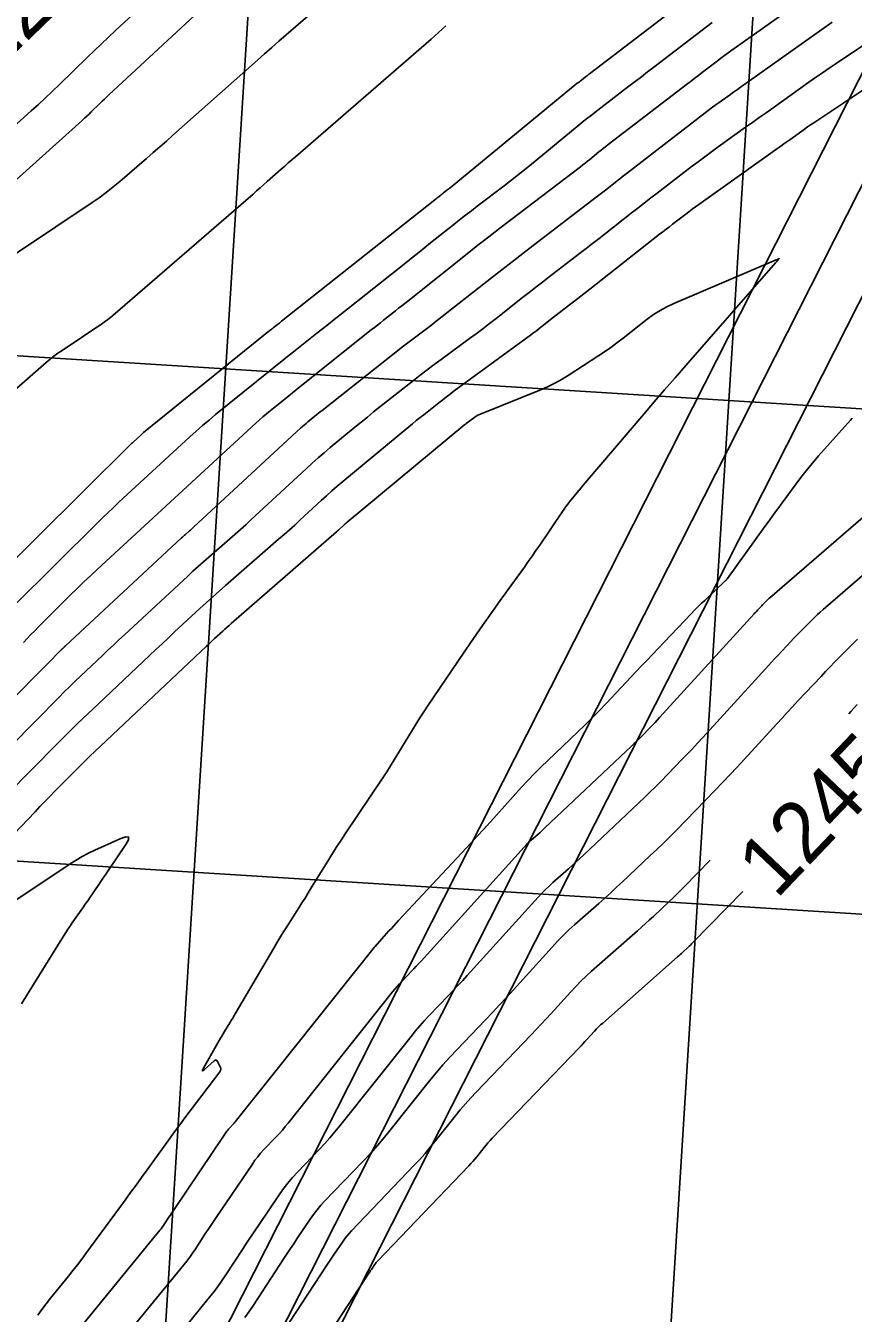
# Model space of a CAD drawing. Extents: x 658976 to 668726, y 639543 to 647196.
# Drawn here: x 662213 to 662295, y 641921 to 642048.7 of the extents above; entities that cross this region are included whole.
import ezdxf

# ---------------------------------------------------------------- set-up
doc = ezdxf.new("R2010")
doc.units = 0
for name, color, linetype in [('Ex_Contour Labels', 7, 'Continuous'), ('Ex_Major Contours', 7, 'Continuous'), ('Ex_Minor Contours', 7, 'Continuous'), ('R_Grid', 7, 'Continuous'), ('R_Water', 7, 'Continuous')]:
    doc.layers.add(name, color=color, linetype=linetype)

msp = doc.modelspace()

# ---------------------------------------------------------------- linework, layer by layer
at = {"layer": 'Ex_Major Contours'}
for points in [[(662209.33, 641993.3), (662223.36, 642007.19), (662223.42, 642007.25), (662223.48, 642007.31), (662223.54, 642007.36), (662223.6, 642007.42), (662224.37, 642008.13), (662224.43, 642008.19), (662224.5, 642008.26), (662224.57, 642008.32), (662224.65, 642008.37), (662237.08, 642018.42), (662237.18, 642018.5), (662237.29, 642018.59), (662237.39, 642018.67), (662237.49, 642018.75), (662237.91, 642019.08), (662238.01, 642019.16), (662238.11, 642019.24), (662238.22, 642019.33), (662238.32, 642019.41), (662253.53, 642031.47), (662253.61, 642031.53), (662253.68, 642031.59), (662253.75, 642031.64), (662253.82, 642031.7), (662254.11, 642031.93), (662254.18, 642031.99), (662254.25, 642032.05), (662254.33, 642032.1), (662254.4, 642032.16), (662254.73, 642032.41), (662254.81, 642032.47), (662254.89, 642032.53), (662254.97, 642032.6), (662255.05, 642032.66), (662267.66, 642043.01), (662267.76, 642043.09), (662267.86, 642043.17), (662267.96, 642043.25), (662268.06, 642043.33), (662268.46, 642043.64), (662268.57, 642043.72), (662268.67, 642043.79), (662268.77, 642043.87), (662268.87, 642043.95), (662282.33, 642054.26)], [(662254.61, 642048.72), (662254.26, 642048.38), (662253.9, 642048.04), (662253.53, 642047.71), (662253.16, 642047.39), (662239.7, 642035.73), (662239.34, 642035.42), (662238.99, 642035.11), (662238.64, 642034.81), (662238.29, 642034.5), (662236.9, 642033.26), (662236.55, 642032.95), (662236.2, 642032.64), (662235.85, 642032.34), (662235.5, 642032.03), (662221.6, 642020), (662221.36, 642019.79), (662221.11, 642019.6), (662220.86, 642019.41), (662220.6, 642019.23), (662216.56, 642016.53), (662216.15, 642016.25), (662215.75, 642015.96), (662215.37, 642015.65), (662214.99, 642015.33), (662202.95, 642004.83)], [(662211.09, 641972.45), (662216.02, 641977.45), (662217.04, 641978.47), (662218.07, 641979.49), (662219.11, 641980.49), (662220.16, 641981.49), (662225.23, 641986.26), (662225.85, 641986.85), (662226.47, 641987.43), (662227.1, 641988.01), (662227.72, 641988.6), (662230.23, 641990.92), (662230.86, 641991.5), (662231.49, 641992.07), (662232.13, 641992.64), (662232.77, 641993.21), (662238.03, 641997.79), (662238.57, 641998.26), (662239.1, 641998.74), (662239.63, 641999.21), (662240.15, 641999.7), (662242.25, 642001.63), (662242.77, 642002.11), (662243.3, 642002.59), (662243.84, 642003.05), (662244.39, 642003.51), (662250.95, 642008.95), (662251.32, 642009.25), (662251.69, 642009.56), (662252.06, 642009.86), (662252.44, 642010.15), (662253.94, 642011.34), (662254.32, 642011.63), (662254.7, 642011.93), (662255.08, 642012.21), (662255.46, 642012.5), (662263.03, 642018.05), (662263.32, 642018.27), (662263.6, 642018.48), (662263.89, 642018.7), (662264.17, 642018.92), (662265.31, 642019.81), (662265.59, 642020.04), (662265.87, 642020.26), (662266.16, 642020.48), (662266.44, 642020.7), (662267.7, 642021.66), (662268, 642021.9), (662268.31, 642022.13), (662268.61, 642022.37), (662268.91, 642022.61), (662275.82, 642028.04), (662276.15, 642028.29), (662276.47, 642028.54), (662276.79, 642028.79), (662277.11, 642029.04), (662278.41, 642030.03), (662278.73, 642030.28), (662279.06, 642030.52), (662279.39, 642030.77), (662279.72, 642031), (662287.54, 642036.58), (662287.84, 642036.79), (662288.13, 642037), (662288.43, 642037.21), (662288.72, 642037.42), (662289.91, 642038.26), (662290.2, 642038.47), (662290.5, 642038.68), (662290.8, 642038.88), (662291.1, 642039.08), (662298.86, 642044.25)], [(662294.93, 642009.82), (662294.74, 642009.61), (662291.59, 642006.07), (662291.11, 642005.51), (662290.64, 642004.95), (662290.18, 642004.37), (662289.74, 642003.79), (662287.99, 642001.42), (662287.55, 642000.83), (662287.12, 642000.24), (662286.69, 641999.64), (662286.26, 641999.05), (662282.55, 641993.9), (662282.53, 641993.88), (662282.52, 641993.86), (662282.5, 641993.84), (662282.48, 641993.82), (662282.41, 641993.74), (662282.39, 641993.72), (662282.37, 641993.7), (662282.35, 641993.69), (662282.33, 641993.67), (662280.29, 641991.74), (662279.95, 641991.42), (662279.61, 641991.08), (662279.28, 641990.75), (662278.94, 641990.4), (662276.26, 641987.58), (662275.7, 641987), (662275.15, 641986.41), (662274.59, 641985.82), (662274.04, 641985.24), (662270.53, 641981.51), (662269.84, 641980.79), (662269.14, 641980.08), (662268.44, 641979.38), (662267.72, 641978.69), (662264.73, 641975.87), (662264.06, 641975.22), (662263.41, 641974.56), (662262.76, 641973.89), (662262.13, 641973.2), (662259.64, 641970.44), (662259.01, 641969.75), (662258.39, 641969.06), (662257.76, 641968.38), (662257.12, 641967.69), (662249.93, 641959.98), (662249.7, 641959.73), (662249.46, 641959.47), (662249.22, 641959.21), (662248.98, 641958.95), (662247.58, 641957.39), (662247.56, 641957.38), (662247.55, 641957.37), (662247.52, 641957.34), (662247.51, 641957.33), (662247.51, 641957.32), (662247.5, 641957.32), (662247.5, 641957.31), (662233.87, 641940.18), (662233.79, 641940.08), (662233.7, 641939.98), (662233.62, 641939.88), (662233.53, 641939.78), (662233.17, 641939.41), (662233.08, 641939.31), (662232.99, 641939.21), (662232.91, 641939.11), (662232.84, 641939), (662227.6, 641931.24), (662227.49, 641931.07), (662227.38, 641930.91), (662227.27, 641930.74), (662227.16, 641930.58), (662226.72, 641929.91), (662226.61, 641929.75), (662226.5, 641929.59), (662226.38, 641929.43), (662226.26, 641929.28), (662218.32, 641919.57)], [(662284.07, 641962.88), (662279.11, 641957.8), (662278.99, 641957.68), (662278.87, 641957.56), (662278.74, 641957.44), (662278.62, 641957.32), (662278.12, 641956.84), (662277.99, 641956.73), (662277.86, 641956.61), (662277.74, 641956.5), (662277.61, 641956.38), (662270.18, 641949.82), (662269.97, 641949.63), (662269.76, 641949.44), (662269.56, 641949.24), (662269.37, 641949.03), (662268.61, 641948.19), (662268.42, 641947.98), (662268.22, 641947.77), (662268.03, 641947.56), (662267.83, 641947.36), (662259.21, 641938.39), (662259, 641938.17), (662258.8, 641937.95), (662258.61, 641937.72), (662258.42, 641937.49), (662257.68, 641936.56), (662257.49, 641936.33), (662257.3, 641936.1), (662257.1, 641935.88), (662256.89, 641935.66), (662247.9, 641926.28), (662247.81, 641926.17), (662247.72, 641926.07), (662247.63, 641925.96), (662247.55, 641925.84), (662247.24, 641925.38), (662247.16, 641925.27), (662247.09, 641925.15), (662247.01, 641925.04), (662246.93, 641924.92), (662240.34, 641914.84)]]:
    msp.add_lwpolyline(points, dxfattribs=at)
at = {"layer": 'Ex_Minor Contours'}
for points in [[(662228.37, 642054.31), (662221.86, 642048.26), (662221.16, 642047.6), (662220.46, 642046.94), (662219.76, 642046.27), (662219.07, 642045.6), (662216.31, 642042.91), (662215.62, 642042.24), (662214.92, 642041.58), (662214.21, 642040.92), (662213.5, 642040.28), (662209.58, 642036.77)], [(662234.16, 642053.9), (662221.2, 642041.86), (662220.98, 642041.65), (662220.76, 642041.44), (662220.54, 642041.23), (662220.32, 642041.02), (662219.45, 642040.17), (662219.23, 642039.96), (662219.01, 642039.75), (662218.79, 642039.54), (662218.56, 642039.34), (662210.03, 642031.7)], [(662212.73, 641987.57), (662213.1, 641987.96), (662213.47, 641988.35), (662213.85, 641988.73), (662214.23, 641989.12), (662217.41, 641992.27), (662218.07, 641992.92), (662218.73, 641993.56), (662219.41, 641994.2), (662220.08, 641994.83), (662235.76, 642009.3), (662236.11, 642009.62), (662236.46, 642009.93), (662236.82, 642010.24), (662237.19, 642010.54), (662238.67, 642011.73), (662239.04, 642012.03), (662239.41, 642012.33), (662239.78, 642012.62), (662240.15, 642012.92), (662247.23, 642018.55), (662247.53, 642018.79), (662247.83, 642019.03), (662248.13, 642019.27), (662248.44, 642019.51), (662249.64, 642020.46), (662249.94, 642020.7), (662250.24, 642020.94), (662250.54, 642021.18), (662250.84, 642021.42), (662256.72, 642026.09), (662257.8, 642026.95), (662258.89, 642027.8), (662259.98, 642028.64), (662261.07, 642029.48), (662267.99, 642034.74), (662268.22, 642034.92), (662268.45, 642035.1), (662268.68, 642035.28), (662268.9, 642035.47), (662269.8, 642036.21), (662270.03, 642036.39), (662270.26, 642036.57), (662270.49, 642036.75), (662270.72, 642036.93), (662278.63, 642043), (662278.99, 642043.27), (662279.35, 642043.55), (662279.71, 642043.83), (662280.08, 642044.11), (662281.53, 642045.22), (662281.89, 642045.49), (662282.25, 642045.76), (662282.62, 642046.03), (662282.99, 642046.3), (662292.11, 642052.79)], [(662241.66, 642050.3), (662238.79, 642047.81), (662238.07, 642047.19), (662237.35, 642046.56), (662236.64, 642045.94), (662235.93, 642045.3), (662227.56, 642037.87), (662226.9, 642037.29), (662226.25, 642036.72), (662225.59, 642036.14), (662224.93, 642035.57), (662222.3, 642033.29), (662221.63, 642032.73), (662220.94, 642032.19), (662220.24, 642031.67), (662219.53, 642031.18), (662204.99, 642021.46)], [(662200.5, 641970.61), (662213.95, 641984.28), (662214.22, 641984.54), (662214.48, 641984.8), (662214.74, 641985.07), (662215, 641985.33), (662216.49, 641986.85), (662216.53, 641986.88), (662216.56, 641986.92), (662216.59, 641986.95), (662216.63, 641986.98), (662216.77, 641987.11), (662216.8, 641987.14), (662216.84, 641987.18), (662216.87, 641987.21), (662216.91, 641987.24), (662228.42, 641997.93), (662228.51, 641998.01), (662228.61, 641998.1), (662228.71, 641998.19), (662228.81, 641998.28), (662229.21, 641998.63), (662229.31, 641998.71), (662229.41, 641998.8), (662229.51, 641998.89), (662229.6, 641998.98), (662240.25, 642008.83), (662240.42, 642008.99), (662240.59, 642009.14), (662240.76, 642009.29), (662240.93, 642009.43), (662241.63, 642010.01), (662241.81, 642010.16), (662241.98, 642010.3), (662242.16, 642010.44), (662242.34, 642010.58), (662250.31, 642016.88), (662250.57, 642017.08), (662250.84, 642017.29), (662251.1, 642017.49), (662251.37, 642017.68), (662252.44, 642018.47), (662252.71, 642018.67), (662252.98, 642018.87), (662253.24, 642019.07), (662253.5, 642019.28), (662259.15, 642023.71), (662260.18, 642024.52), (662261.21, 642025.32), (662262.25, 642026.12), (662263.28, 642026.92), (662269.53, 642031.73), (662269.79, 642031.93), (662270.05, 642032.13), (662270.31, 642032.33), (662270.57, 642032.53), (662271.6, 642033.34), (662271.86, 642033.55), (662272.12, 642033.75), (662272.38, 642033.95), (662272.64, 642034.15), (662281.08, 642040.63), (662281.3, 642040.8), (662281.52, 642040.96), (662281.74, 642041.12), (662281.96, 642041.28), (662282.84, 642041.91), (662283.06, 642042.07), (662283.28, 642042.22), (662283.5, 642042.38), (662283.72, 642042.54), (662292.93, 642049.09)], [(662211.78, 641991.21), (662220.03, 641999.38), (662220.57, 641999.91), (662221.11, 642000.43), (662221.65, 642000.95), (662222.2, 642001.46), (662229.24, 642007.96), (662229.86, 642008.52), (662230.5, 642009.08), (662231.14, 642009.62), (662231.79, 642010.16), (662237.2, 642014.53), (662237.77, 642014.99), (662238.35, 642015.45), (662238.92, 642015.92), (662239.5, 642016.38), (662241.82, 642018.22), (662242.4, 642018.68), (662242.97, 642019.14), (662243.55, 642019.6), (662244.13, 642020.06), (662250.81, 642025.35), (662251.38, 642025.81), (662251.96, 642026.26), (662252.53, 642026.72), (662253.11, 642027.18), (662255.41, 642029.01), (662255.99, 642029.47), (662256.57, 642029.92), (662257.15, 642030.37), (662257.74, 642030.82), (662260.4, 642032.84), (662261.03, 642033.33), (662261.66, 642033.83), (662262.29, 642034.33), (662262.91, 642034.83), (662267.85, 642038.88), (662268.45, 642039.38), (662269.06, 642039.86), (662269.68, 642040.35), (662270.29, 642040.82), (662272.77, 642042.72), (662273.39, 642043.2), (662274.01, 642043.67), (662274.63, 642044.15), (662275.25, 642044.62), (662281.03, 642049.05)], [(662204.24, 641969.97), (662216.26, 641982.15), (662216.78, 641982.68), (662217.32, 641983.2), (662217.85, 641983.72), (662218.39, 641984.23), (662220.57, 641986.28), (662221.11, 641986.79), (662221.65, 641987.3), (662222.2, 641987.81), (662222.75, 641988.32), (662229.02, 641994.14), (662229.54, 641994.62), (662230.05, 641995.09), (662230.57, 641995.55), (662231.1, 641996.01), (662233.2, 641997.85), (662233.73, 641998.31), (662234.25, 641998.77), (662234.77, 641999.24), (662235.28, 641999.71), (662240.77, 642004.79), (662241.36, 642005.33), (662241.95, 642005.86), (662242.55, 642006.37), (662243.16, 642006.89), (662245.61, 642008.92), (662246.22, 642009.42), (662246.84, 642009.92), (662247.46, 642010.42), (662248.08, 642010.92), (662251.42, 642013.55), (662252.09, 642014.08), (662252.77, 642014.6), (662253.46, 642015.12), (662254.15, 642015.63), (662256.95, 642017.69), (662257.62, 642018.18), (662258.29, 642018.68), (662258.95, 642019.19), (662259.61, 642019.7), (662262.23, 642021.76), (662262.89, 642022.28), (662263.54, 642022.79), (662264.2, 642023.3), (662264.86, 642023.81), (662267.89, 642026.14), (662268.54, 642026.64), (662269.18, 642027.13), (662269.82, 642027.63), (662270.46, 642028.13), (662273.01, 642030.14), (662273.65, 642030.64), (662274.29, 642031.14), (662274.94, 642031.64), (662275.58, 642032.13), (662278.96, 642034.73), (662279.63, 642035.24), (662280.29, 642035.73), (662280.97, 642036.23), (662281.64, 642036.71), (662284.35, 642038.65), (662285.03, 642039.13), (662285.71, 642039.61), (662286.39, 642040.1), (662287.07, 642040.58), (662290.62, 642043.11), (662291.29, 642043.58), (662291.96, 642044.05), (662292.64, 642044.51), (662293.32, 642044.97), (662296.05, 642046.78)], [(662214.16, 641920.84), (662214.56, 641921.42), (662214.98, 641921.98), (662215.42, 641922.54), (662217.2, 641924.73), (662217.64, 641925.28), (662218.08, 641925.84), (662218.51, 641926.4), (662218.93, 641926.97), (662222.82, 641932.27), (662223.36, 641933.01), (662223.91, 641933.75), (662224.45, 641934.5), (662224.99, 641935.25), (662227.21, 641938.33), (662227.72, 641939.03), (662228.23, 641939.73), (662228.74, 641940.42), (662229.26, 641941.11), (662232.2, 641944.99), (662232.27, 641945.11), (662232.3, 641945.24), (662232.29, 641945.36), (662232.24, 641945.49), (662231.98, 641946.02), (662231.91, 641946.12), (662231.83, 641946.17), (662231.74, 641946.15), (662231.63, 641946.08), (662230.7, 641945.23), (662230.55, 641945.11), (662230.48, 641945.08), (662230.49, 641945.16), (662230.57, 641945.33), (662232.14, 641948.08), (662232.27, 641948.31), (662232.4, 641948.53), (662232.54, 641948.75), (662232.67, 641948.97), (662233.21, 641949.85), (662233.34, 641950.07), (662233.48, 641950.29), (662233.61, 641950.51), (662233.74, 641950.73), (662237.56, 641957.26), (662237.86, 641957.76), (662238.16, 641958.26), (662238.47, 641958.76), (662238.78, 641959.25), (662240.04, 641961.23), (662240.35, 641961.73), (662240.66, 641962.22), (662240.97, 641962.72), (662241.28, 641963.22), (662243.02, 641966.05), (662243.42, 641966.69), (662243.82, 641967.32), (662244.23, 641967.95), (662244.64, 641968.58), (662248.37, 641974.15), (662248.76, 641974.74), (662249.14, 641975.32), (662249.51, 641975.91), (662249.87, 641976.51), (662251.31, 641978.9), (662251.67, 641979.49), (662252.05, 641980.08), (662252.43, 641980.67), (662252.81, 641981.25), (662257.06, 641987.51), (662257.36, 641987.94), (662257.66, 641988.38), (662257.96, 641988.81), (662258.26, 641989.24), (662259.48, 641990.95), (662259.78, 641991.38), (662260.09, 641991.81), (662260.39, 641992.24), (662260.7, 641992.67), (662262.42, 641995.04), (662262.8, 641995.58), (662263.19, 641996.12), (662263.56, 641996.67), (662263.94, 641997.21), (662266.18, 642000.54), (662266.35, 642000.79), (662266.53, 642001.03), (662266.71, 642001.27), (662266.9, 642001.51), (662267.66, 642002.45), (662267.85, 642002.68), (662268.05, 642002.91), (662268.24, 642003.15), (662268.44, 642003.38), (662274.25, 642010.2), (662275.28, 642011.41), (662276.32, 642012.62), (662277.36, 642013.82), (662278.41, 642015.02), (662287.33, 642025.21), (662287.35, 642025.23), (662287.37, 642025.26), (662287.39, 642025.28), (662287.41, 642025.3), (662287.52, 642025.44), (662287.53, 642025.45), (662287.54, 642025.46), (662287.57, 642025.49), (662287.58, 642025.5), (662287.58, 642025.5), (662287.68, 642025.6), (662287.69, 642025.61), (662287.69, 642025.62), (662287.68, 642025.62), (662287.66, 642025.62), (662287.55, 642025.57), (662287.54, 642025.56), (662287.52, 642025.56), (662287.51, 642025.55), (662287.49, 642025.54), (662287.43, 642025.52), (662287.42, 642025.51), (662287.4, 642025.5), (662287.39, 642025.5), (662287.37, 642025.49), (662277.22, 642021.17), (662276.53, 642020.85), (662275.86, 642020.48), (662275.22, 642020.08), (662274.6, 642019.62), (662272.2, 642017.73), (662271.59, 642017.26), (662270.97, 642016.81), (662270.35, 642016.37), (662269.71, 642015.95), (662266.85, 642014.1), (662266.15, 642013.67), (662265.43, 642013.27), (662264.69, 642012.91), (662263.94, 642012.59), (662258.11, 642010.24), (662257.95, 642010.17), (662257.79, 642010.09), (662257.64, 642009.99), (662257.49, 642009.89), (662256.64, 642009.27), (662256.63, 642009.26), (662256.62, 642009.25), (662256.61, 642009.24), (662256.6, 642009.24), (662256.56, 642009.21), (662256.54, 642009.19), (662256.52, 642009.17), (662244.83, 641999.48), (662244.74, 641999.4), (662244.65, 641999.33), (662244.56, 641999.25), (662244.47, 641999.17), (662244.13, 641998.85), (662244.04, 641998.77), (662243.96, 641998.69), (662243.87, 641998.62), (662243.78, 641998.54), (662233.33, 641989.44), (662233.12, 641989.25), (662232.92, 641989.07), (662232.71, 641988.88), (662232.51, 641988.69), (662231.69, 641987.94), (662231.49, 641987.75), (662231.29, 641987.56), (662231.09, 641987.37), (662230.88, 641987.18), (662219.82, 641976.76), (662219.32, 641976.28), (662218.81, 641975.79), (662218.31, 641975.3), (662217.82, 641974.8), (662215.84, 641972.8), (662215.35, 641972.3), (662214.86, 641971.79), (662214.37, 641971.29), (662213.88, 641970.78), (662203.89, 641960.32)], [(662298.68, 642002.3), (662286.74, 641991.98), (662286.66, 641991.91), (662286.59, 641991.85), (662286.52, 641991.78), (662286.45, 641991.71), (662286.16, 641991.42), (662286.09, 641991.35), (662286.02, 641991.28), (662285.95, 641991.21), (662285.88, 641991.13), (662285.53, 641990.75), (662285.45, 641990.67), (662285.37, 641990.58), (662285.28, 641990.49), (662285.2, 641990.4), (662275.81, 641980.11), (662275.59, 641979.87), (662275.37, 641979.63), (662275.14, 641979.39), (662274.91, 641979.15), (662274, 641978.22), (662273.77, 641977.98), (662273.53, 641977.75), (662273.3, 641977.53), (662273.06, 641977.3), (662264.44, 641969.17), (662264.27, 641969.01), (662264.1, 641968.85), (662263.93, 641968.7), (662263.76, 641968.54), (662263.06, 641967.93), (662262.89, 641967.77), (662262.72, 641967.61), (662262.56, 641967.44), (662262.4, 641967.27), (662252.16, 641955.97), (662251.93, 641955.72), (662251.69, 641955.46), (662251.45, 641955.21), (662251.21, 641954.96), (662250.25, 641953.95), (662250.01, 641953.7), (662249.78, 641953.44), (662249.55, 641953.18), (662249.33, 641952.91), (662238.99, 641939.9), (662238.7, 641939.55), (662238.41, 641939.21), (662238.11, 641938.87), (662237.8, 641938.55), (662236.55, 641937.24), (662236.25, 641936.91), (662235.96, 641936.57), (662235.68, 641936.21), (662235.43, 641935.84), (662231.85, 641930.54), (662231.58, 641930.15), (662231.32, 641929.76), (662231.06, 641929.36), (662230.8, 641928.97), (662229.76, 641927.38), (662229.5, 641926.99), (662229.22, 641926.6), (662228.94, 641926.22), (662228.64, 641925.85), (662222.92, 641918.86)], [(662300.53, 641998.17), (662292.04, 641990.82), (662291.76, 641990.58), (662291.49, 641990.32), (662291.21, 641990.07), (662290.95, 641989.8), (662289.89, 641988.74), (662289.63, 641988.48), (662289.37, 641988.21), (662289.11, 641987.94), (662288.85, 641987.67), (662287.53, 641986.26), (662287.23, 641985.93), (662286.92, 641985.6), (662286.62, 641985.27), (662286.32, 641984.94), (662280.1, 641978.13), (662279.59, 641977.58), (662279.08, 641977.03), (662278.56, 641976.48), (662278.03, 641975.94), (662275.93, 641973.78), (662275.4, 641973.24), (662274.86, 641972.71), (662274.32, 641972.19), (662273.77, 641971.67), (662268.29, 641966.49), (662267.92, 641966.14), (662267.54, 641965.8), (662267.16, 641965.45), (662266.78, 641965.11), (662265.24, 641963.75), (662264.86, 641963.41), (662264.49, 641963.06), (662264.13, 641962.69), (662263.78, 641962.32), (662256.75, 641954.55), (662256.29, 641954.05), (662255.82, 641953.54), (662255.35, 641953.04), (662254.88, 641952.55), (662252.97, 641950.57), (662252.5, 641950.07), (662252.05, 641949.56), (662251.6, 641949.04), (662251.17, 641948.5), (662244.11, 641939.63), (662243.62, 641939.03), (662243.12, 641938.44), (662242.61, 641937.87), (662242.08, 641937.31), (662239.94, 641935.08), (662239.42, 641934.51), (662238.93, 641933.92), (662238.46, 641933.31), (662238.01, 641932.68), (662236.1, 641929.85), (662235.68, 641929.23), (662235.26, 641928.6), (662234.85, 641927.98), (662234.44, 641927.35), (662232.8, 641924.84), (662232.38, 641924.22), (662231.95, 641923.61), (662231.5, 641923.02), (662231.03, 641922.43), (662227.53, 641918.15)], [(662295.45, 641987.9), (662293.62, 641986.06), (662293.17, 641985.6), (662292.72, 641985.14), (662292.27, 641984.67), (662291.83, 641984.2), (662289.54, 641981.76), (662289.01, 641981.19), (662288.48, 641980.62), (662287.96, 641980.06), (662287.44, 641979.49), (662284.22, 641975.96), (662283.51, 641975.19), (662282.79, 641974.42), (662282.07, 641973.66), (662281.34, 641972.91), (662277.46, 641968.93), (662276.83, 641968.3), (662276.19, 641967.66), (662275.55, 641967.04), (662274.9, 641966.42), (662272.14, 641963.82), (662271.56, 641963.28), (662270.98, 641962.74), (662270.39, 641962.21), (662269.8, 641961.68), (662267.42, 641959.58), (662266.83, 641959.05), (662266.26, 641958.5), (662265.71, 641957.94), (662265.17, 641957.36), (662261.34, 641953.13), (662260.65, 641952.37), (662259.95, 641951.62), (662259.25, 641950.88), (662258.54, 641950.14), (662255.7, 641947.18), (662255, 641946.44), (662254.32, 641945.67), (662253.65, 641944.9), (662253, 641944.1), (662249.23, 641939.36), (662248.54, 641938.51), (662247.83, 641937.68), (662247.1, 641936.86), (662246.36, 641936.07), (662242.63, 641932.18), (662242.23, 641931.75), (662241.86, 641931.3), (662241.5, 641930.84), (662241.16, 641930.36), (662239.85, 641928.42), (662239.53, 641927.94), (662239.2, 641927.45), (662238.88, 641926.96), (662238.56, 641926.48), (662235.54, 641921.85), (662235.12, 641921.23), (662234.68, 641920.62)], [(662295.43, 641981.4), (662294.8, 641980.73), (662294.58, 641980.5)], [(662212.52, 641951.71), (662216.7, 641958.44), (662216.93, 641958.8), (662217.16, 641959.15), (662217.4, 641959.5), (662217.64, 641959.85), (662218.62, 641961.25), (662218.86, 641961.6), (662219.1, 641961.94), (662219.35, 641962.3), (662219.58, 641962.65), (662222.88, 641967.53), (662223.14, 641968), (662223.15, 641968.26), (662222.89, 641968.3), (662222.38, 641968.12), (662219.82, 641966.96), (662219.18, 641966.66), (662218.56, 641966.33), (662217.96, 641965.98), (662217.36, 641965.6), (662207.29, 641958.9)], [(662280.83, 641965.97), (662278.28, 641963.37), (662277.91, 641962.99), (662277.53, 641962.61), (662277.15, 641962.24), (662276.76, 641961.87), (662275.2, 641960.4), (662274.81, 641960.04), (662274.42, 641959.68), (662274.02, 641959.32), (662273.63, 641958.96), (662269.08, 641954.95), (662268.54, 641954.46), (662268.02, 641953.96), (662267.51, 641953.45), (662267.02, 641952.92), (662265.07, 641950.77), (662264.58, 641950.23), (662264.09, 641949.7), (662263.59, 641949.17), (662263.09, 641948.64), (662257.64, 641942.98), (662257.09, 641942.4), (662256.56, 641941.81), (662256.05, 641941.21), (662255.55, 641940.59), (662253.57, 641938.11), (662253.07, 641937.5), (662252.56, 641936.89), (662252.03, 641936.3), (662251.49, 641935.72), (662245.26, 641929.23), (662245.02, 641928.96), (662244.79, 641928.68), (662244.57, 641928.4), (662244.36, 641928.1), (662243.55, 641926.9), (662243.35, 641926.6), (662243.14, 641926.3), (662242.94, 641926), (662242.75, 641925.7), (662237.94, 641918.34)]]:
    msp.add_lwpolyline(points, dxfattribs=at)
at = {"layer": 'R_Grid'}
for p, q in [((662220.25, 641815.08), (662235.92, 642064.59)), ((662270.15, 641811.95), (662285.82, 642061.45)), ((661633.97, 642052.3), (663131.02, 641958.27)), ((661630.83, 642002.39), (663127.88, 641908.37))]:
    msp.add_line(p, q, dxfattribs=at)
at = {"layer": 'R_Water'}
for p, q in [((662216.73, 641887.88), (662333.31, 642117.78)), ((662221.19, 641885.62), (662337.77, 642115.51)), ((662225.65, 641883.36), (662342.23, 642113.25))]:
    msp.add_line(p, q, dxfattribs=at)

# ---------------------------------------------------------------- texts
at = {"layer": 'Ex_Contour Labels'}
for s, rotation, p in [('1250', 44.0614, (662209.74, 642043.91)), ('1245', 46.4122, (662287.4, 641962.02))]:
    msp.add_text(s, height=6, rotation=rotation, dxfattribs=at).set_placement(p)

doc.saveas('drawing.dxf')
